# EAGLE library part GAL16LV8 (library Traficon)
3.3V GAL16V8 in footprint for PLCC20 package
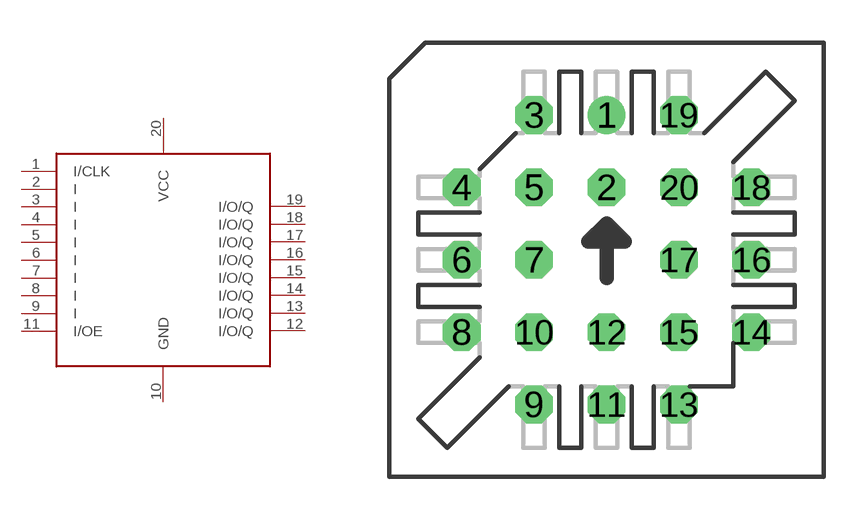
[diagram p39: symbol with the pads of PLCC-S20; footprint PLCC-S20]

Designator prefix IC

## GAL16LV8  [PLCC-S20]
1  I/CLK
2  I  in
3  I  in
4  I  in
5  I  in
6  I  in
7  I  in
8  I  in
9  I  in
10  GND  pas
11  I/OE
12  I/O/Q
13  I/O/Q
14  I/O/Q
15  I/O/Q
16  I/O/Q
17  I/O/Q
18  I/O/Q
19  I/O/Q
20  VCC  pas

## Footprint PLCC-S20 (pad centres in mm)
Plastic Leaded Chip Carrier Socked
drill 0.813 round: 1 0,5.08
drill 0.813 octagon: 2 0,2.54; 3 -2.54,5.08; 4 -5.08,2.54; 5 -2.54,2.54; 6 -5.08,0; 7 -2.54,0; 8 -5.08,-2.54; 9 -2.54,-5.08; 10 -2.54,-2.54; 11 0,-5.08; 12 0,-2.54; 13 2.54,-5.08; 14 5.08,-2.54; 15 2.54,-2.54; 16 5.08,0; 17 2.54,0; 18 5.08,2.54; 19 2.54,5.08; 20 2.54,2.54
